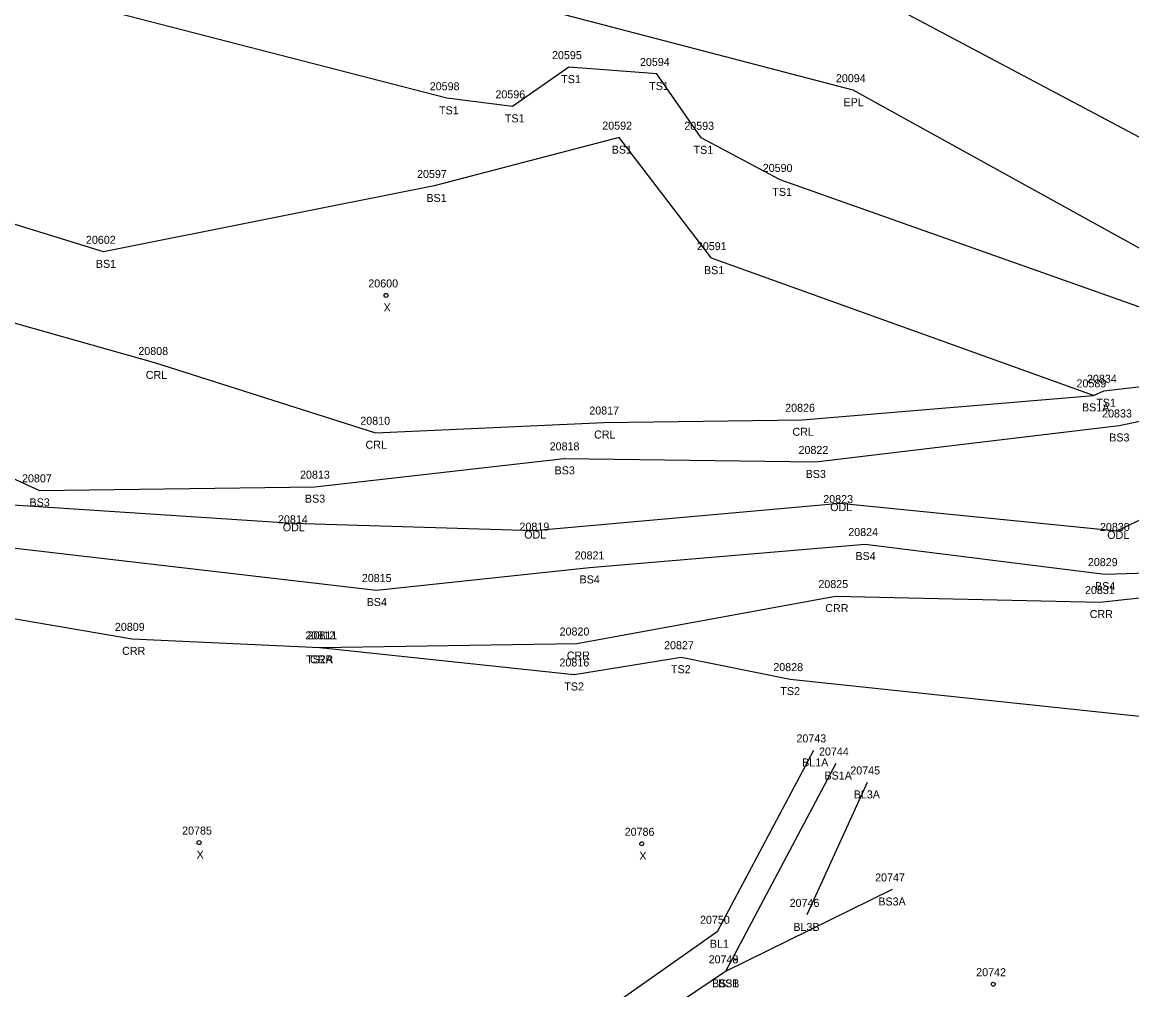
# Model space of a CAD drawing. Extents: x 1813127 to 1814107, y 1178171 to 1179078.
# Drawn here: x 1813586.1 to 1813724.7, y 1178619.3 to 1178740.3 of the extents above; entities that cross this region are included whole.
import ezdxf

# ---------------------------------------------------------------- set-up
doc = ezdxf.new("R2010")
doc.units = 0
for name, color, linetype in [('RD_DTM_BkLn1', 7, 'Continuous'), ('RD_DTM_BkLn2', 7, 'Continuous'), ('RD_EX_H2O', 7, 'Continuous'), ('RD_EX_H2O_txCode', 7, 'Continuous'), ('RD_EX_Road', 7, 'Continuous'), ('RD_EX_Road_txCode', 7, 'Continuous'), ('RD_SMD_Locator', 7, 'Continuous'), ('RD_SMD_Misc', 7, 'Continuous')]:
    doc.layers.add(name, color=color, linetype=linetype)

msp = doc.modelspace()

# ---------------------------------------------------------------- linework, layer by layer
at = {"layer": 'RD_DTM_BkLn1'}
msp.add_line((1813691.64, 1178645.24), (1813684.08, 1178628.68), dxfattribs=at)
for points in [[(1813740.76, 1178717.86), (1813693.97, 1178742.65), (1813652.18, 1178753.85), (1813643.74, 1178755.64), (1813595, 1178763.51), (1813546.44, 1178770.61), (1813497.6, 1178777.62), (1813448.59, 1178785.89), (1813401.09, 1178795.04), (1813353.48, 1178806.76), (1813306.05, 1178819.85), (1813260.03, 1178834.12), (1813213.64, 1178849.47), (1813166.61, 1178866.29)], [(1813684.91, 1178649.24), (1813672.9, 1178626.57), (1813636.59, 1178600.97), (1813597.02, 1178573.71), (1813553.38, 1178551.14), (1813526.62, 1178527.89)]]:
    msp.add_lwpolyline(points, dxfattribs=at)
at = {"layer": 'RD_DTM_BkLn2'}
msp.add_line((1813694.73, 1178631.86), (1813673.94, 1178621.63), dxfattribs=at)
for points in [[(1813728.98, 1178703.48), (1813680.74, 1178720.54), (1813670.9, 1178725.8), (1813665.35, 1178733.78), (1813654.36, 1178734.63), (1813647.32, 1178729.73), (1813639.1, 1178730.74), (1813591.11, 1178743.16), (1813543.28, 1178751.57), (1813511.7, 1178756.57), (1813494.92, 1178760.32), (1813445.74, 1178769.42), (1813422.91, 1178772.94), (1813422.78, 1178770.34)], [(1813501.61, 1178700.78), (1813535.62, 1178707.92), (1813578.65, 1178686.08), (1813588.2, 1178681.74), (1813622.61, 1178682.2), (1813653.79, 1178685.74), (1813685.17, 1178685.29), (1813723.1, 1178689.85), (1813736.83, 1178692.71), (1813771.26, 1178719.75), (1813784.46, 1178726.39), (1813801.14, 1178736.57), (1813819.08, 1178738.18), (1813840.25, 1178734.78), (1813848.44, 1178735.38), (1813862.15, 1178734.12), (1813885.61, 1178732.56), (1813903.34, 1178733.15)], [(1813719.9, 1178693.61), (1813672.18, 1178710.76), (1813660.65, 1178725.82), (1813637.51, 1178719.78), (1813596.2, 1178711.55), (1813573.69, 1178718.5), (1813539.15, 1178731.18), (1813521.54, 1178735.83), (1813479.61, 1178734.97)], [(1813494.55, 1178680.43), (1813533.86, 1178695.27), (1813573.03, 1178675.94), (1813630.33, 1178669.28), (1813656.92, 1178672.11), (1813691.39, 1178675.03), (1813721.31, 1178671.27), (1813738.7, 1178671.81), (1813780.2, 1178710.54), (1813805.93, 1178727.26), (1813819.91, 1178727.35), (1813841.4, 1178723.71), (1813860.66, 1178719.9), (1813869.89, 1178724.9), (1813872.35, 1178725.71), (1813884.47, 1178724.42), (1813903.61, 1178724.04)], [(1813623.26, 1178662.12), (1813655.04, 1178658.73), (1813668.37, 1178660.89), (1813682.02, 1178658.15), (1813729.97, 1178653.08)], [(1813687.73, 1178647.6), (1813673.94, 1178621.63), (1813639.04, 1178598.07), (1813598.95, 1178570.83), (1813556.33, 1178547.73), (1813528.18, 1178524.13)]]:
    msp.add_lwpolyline(points, dxfattribs=at)
at = {"layer": 'RD_EX_H2O'}
for points in [[(1813497.15, 1178691.5), (1813535.61, 1178703.5), (1813575.96, 1178680.52), (1813619.86, 1178677.62), (1813650.02, 1178676.71), (1813688.26, 1178680.15), (1813722.87, 1178676.67), (1813738.45, 1178684.24), (1813776.33, 1178715.9), (1813785.2, 1178724.07), (1813802.21, 1178734.6), (1813820.03, 1178732.78), (1813837.63, 1178729.78), (1813857.38, 1178730.32)], [(1813721.21, 1178694.19), (1813733.77, 1178695.63), (1813767.86, 1178725.16), (1813778.94, 1178729.95)], [(1813499.62, 1178706.37), (1813533.11, 1178716.31), (1813566.87, 1178706.45), (1813581.02, 1178703.79), (1813602.73, 1178697.66), (1813630.18, 1178688.94), (1813658.74, 1178690.22), (1813683.52, 1178690.56), (1813719.9, 1178693.61)], [(1813719.9, 1178693.61), (1813721.21, 1178694.19)], [(1813494.93, 1178677.14), (1813538.08, 1178685.02), (1813548.67, 1178684.4), (1813554.06, 1178674.83), (1813572.78, 1178667.8), (1813599.8, 1178663.18), (1813623.26, 1178662.12), (1813655.35, 1178662.6), (1813687.65, 1178668.53), (1813720.68, 1178667.78), (1813740.16, 1178669.89)]]:
    msp.add_lwpolyline(points, dxfattribs=at)
at = {"layer": 'RD_EX_Road'}
msp.add_lwpolyline([(1813732.94, 1178707.95), (1813689.88, 1178731.75), (1813641.71, 1178744.36), (1813593.37, 1178752.09), (1813544.49, 1178758.77), (1813495.45, 1178766.29), (1813446.8, 1178774.66), (1813426.54, 1178777.95), (1813403.21, 1178782.55), (1813398.65, 1178783.84), (1813350.68, 1178796.09), (1813343.23, 1178797.92), (1813318.7, 1178804.23), (1813303.26, 1178808.85), (1813256.8, 1178823.17), (1813209.81, 1178838.91), (1813163.27, 1178855.57)], dxfattribs=at)
at = {"layer": 'RD_SMD_Locator'}
for centre, radius in [((1813654.36, 1178734.63), 0.001), ((1813665.35, 1178733.78), 0.001), ((1813689.88, 1178731.75), 0.001), ((1813639.1, 1178730.74), 0.001), ((1813647.32, 1178729.73), 0.001), ((1813660.65, 1178725.82), 0.001), ((1813670.9, 1178725.8), 0.001), ((1813680.74, 1178720.54), 0.001), ((1813637.51, 1178719.78), 0.001), ((1813596.2, 1178711.55), 0.001), ((1813672.18, 1178710.76), 0.001), ((1813631.52, 1178706.1), 0.25), ((1813602.73, 1178697.66), 0.001), ((1813721.21, 1178694.19), 0.001), ((1813719.9, 1178693.61), 0.001), ((1813658.74, 1178690.22), 0.001), ((1813683.52, 1178690.56), 0.001), ((1813630.18, 1178688.94), 0.001), ((1813723.1, 1178689.85), 0.001), ((1813653.79, 1178685.74), 0.001), ((1813685.17, 1178685.29), 0.001), ((1813588.2, 1178681.74), 0.001), ((1813622.61, 1178682.2), 0.001), ((1813688.26, 1178680.15), 0.001), ((1813619.86, 1178677.62), 0.001), ((1813650.02, 1178676.71), 0.001), ((1813722.87, 1178676.67), 0.001), ((1813691.39, 1178675.03), 0.001), ((1813656.92, 1178672.11), 0.001), ((1813721.31, 1178671.27), 0.001), ((1813630.33, 1178669.28), 0.001), ((1813687.65, 1178668.53), 0.001), ((1813720.68, 1178667.78), 0.001), ((1813599.8, 1178663.18), 0.001), ((1813655.35, 1178662.6), 0.001), ((1813623.26, 1178662.12), 0.001), ((1813623.26, 1178662.12), 0.001), ((1813668.37, 1178660.89), 0.001), ((1813655.04, 1178658.73), 0.001), ((1813682.02, 1178658.15), 0.001), ((1813684.91, 1178649.24), 0.001), ((1813687.73, 1178647.6), 0.001), ((1813691.64, 1178645.24), 0.001), ((1813608.16, 1178637.72), 0.25), ((1813663.47, 1178637.57), 0.25), ((1813694.73, 1178631.86), 0.001), ((1813684.08, 1178628.68), 0.001), ((1813672.9, 1178626.57), 0.001), ((1813673.94, 1178621.63), 0.001), ((1813673.94, 1178621.63), 0.001), ((1813707.37, 1178620.02), 0.25)]:
    msp.add_circle(centre, radius, dxfattribs=at)

# ---------------------------------------------------------------- texts
at = {"layer": 'RD_EX_H2O_txCode'}
for s, p in [('20808', (1813600.57, 1178698.66)), ('CRL', (1813601.5, 1178695.66)), ('20817', (1813656.91, 1178691.22)), ('20826', (1813681.38, 1178691.56)), ('20810', (1813628.3, 1178689.94)), ('CRL', (1813657.51, 1178688.22)), ('CRL', (1813682.29, 1178688.56)), ('CRL', (1813628.95, 1178686.94)), ('20823', (1813686.14, 1178680.15)), ('ODL', (1813687.01, 1178679.15)), ('20814', (1813618.02, 1178677.62)), ('ODL', (1813618.62, 1178676.62)), ('20819', (1813648.19, 1178676.71)), ('20830', (1813720.71, 1178676.67)), ('ODL', (1813648.78, 1178675.71)), ('ODL', (1813721.62, 1178675.67)), ('20825', (1813685.53, 1178669.53)), ('20831', (1813718.84, 1178668.78)), ('CRR', (1813686.39, 1178666.53)), ('CRR', (1813719.43, 1178665.78)), ('20809', (1813597.64, 1178664.18)), ('20811', (1813621.71, 1178663.12)), ('20820', (1813653.2, 1178663.6)), ('CRR', (1813598.54, 1178661.18)), ('CRR', (1813622.01, 1178660.12)), ('CRR', (1813654.1, 1178660.6))]:
    msp.add_text(s, height=1, dxfattribs=at).set_placement(p)
at = {"layer": 'RD_EX_Road_txCode'}
for s, p in [('20094', (1813687.72, 1178732.75)), ('EPL', (1813688.68, 1178729.75))]:
    msp.add_text(s, height=1, dxfattribs=at).set_placement(p)
at = {"layer": 'RD_SMD_Misc'}
for s, p in [('20595', (1813652.25, 1178735.63)), ('20594', (1813663.24, 1178734.78)), ('TS1', (1813653.4, 1178732.63)), ('20598', (1813636.98, 1178731.74)), ('20596', (1813645.18, 1178730.73)), ('TS1', (1813664.39, 1178731.78)), ('TS1', (1813638.14, 1178728.74)), ('TS1', (1813646.36, 1178727.73)), ('20592', (1813658.53, 1178726.82)), ('20593', (1813668.78, 1178726.8)), ('BS1', (1813659.71, 1178723.82)), ('TS1', (1813669.94, 1178723.8)), ('20590', (1813678.58, 1178721.54)), ('20597', (1813635.39, 1178720.78)), ('TS1', (1813679.78, 1178718.54)), ('BS1', (1813636.56, 1178717.78)), ('20602', (1813594.02, 1178712.55)), ('20591', (1813670.35, 1178711.76)), ('BS1', (1813595.26, 1178709.55)), ('BS1', (1813671.24, 1178708.76)), ('20600', (1813629.3, 1178707.1)), ('X', (1813631.21, 1178704.1)), ('20589', (1813717.78, 1178694.61)), ('20834', (1813719.09, 1178695.19)), ('TS1', (1813720.25, 1178692.19)), ('BS1A', (1813718.47, 1178691.61)), ('20833', (1813720.98, 1178690.85)), ('BS3', (1813721.87, 1178687.85)), ('20818', (1813651.96, 1178686.74)), ('20822', (1813683.05, 1178686.29)), ('BS3', (1813652.57, 1178683.74)), ('20807', (1813586.04, 1178682.74)), ('20813', (1813620.77, 1178683.2)), ('BS3', (1813683.94, 1178683.29)), ('BS3', (1813586.97, 1178679.74)), ('BS3', (1813621.38, 1178680.2)), ('20824', (1813689.27, 1178676.03)), ('20821', (1813655.08, 1178673.11)), ('BS4', (1813690.16, 1178673.03)), ('20829', (1813719.2, 1178672.27)), ('20815', (1813628.49, 1178670.28)), ('BS4', (1813655.69, 1178670.11)), ('BS4', (1813720.09, 1178669.27)), ('BS4', (1813629.1, 1178667.28)), ('20812', (1813621.43, 1178663.12)), ('20827', (1813666.25, 1178661.89)), ('TS2A', (1813621.53, 1178660.12)), ('20816', (1813653.18, 1178659.73)), ('TS2', (1813667.12, 1178658.89)), ('20828', (1813679.9, 1178659.15)), ('TS2', (1813653.79, 1178656.73)), ('TS2', (1813680.78, 1178656.15)), ('20743', (1813682.79, 1178650.24)), ('20744', (1813685.61, 1178648.6)), ('BL1A', (1813683.5, 1178647.24)), ('20745', (1813689.52, 1178646.24)), ('BS1A', (1813686.29, 1178645.6)), ('BL3A', (1813689.95, 1178643.24)), ('20785', (1813606.04, 1178638.72)), ('20786', (1813661.33, 1178638.57)), ('X', (1813607.85, 1178635.72)), ('X', (1813663.16, 1178635.57)), ('20747', (1813692.62, 1178632.86)), ('20746', (1813681.94, 1178629.68)), ('BS3A', (1813693.02, 1178629.86)), ('20750', (1813670.74, 1178627.57)), ('BL3B', (1813682.41, 1178626.68)), ('BL1', (1813671.98, 1178624.57)), ('20748', (1813671.82, 1178622.63)), ('20749', (1813671.82, 1178622.63)), ('20742', (1813705.25, 1178621.02)), ('BS3B', (1813672.24, 1178619.63)), ('BS1', (1813672.99, 1178619.63))]:
    msp.add_text(s, height=1, dxfattribs=at).set_placement(p)

doc.saveas('drawing.dxf')
